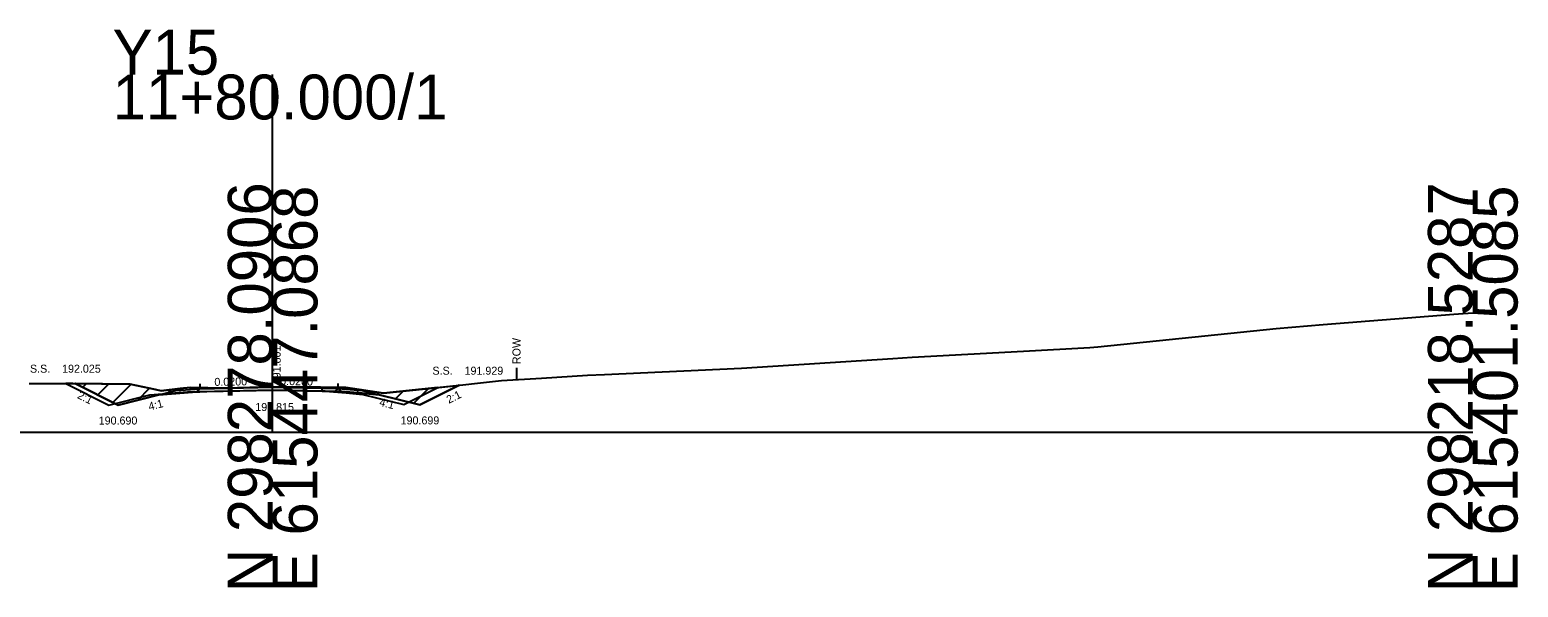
# Model space of a CAD drawing. Extents: x 517327 to 517505, y 114839 to 116885.
# Drawn here: x 517412.2 to 517505.2, y 115838.7 to 115873.5 of the extents above; entities that cross this region are included whole.
import ezdxf

# ---------------------------------------------------------------- set-up
doc = ezdxf.new("R2010")
doc.units = 0
for name, color, linetype in [('Exist XS Ground Line', 7, 'Continuous'), ('Old_Level_60', 7, 'Continuous'), ('Old_Level_63', 7, 'Continuous'), ('Prop XS Dump Level', 7, 'Continuous'), ('Prop XS Earthwork Shape', 7, 'Continuous'), ('Prop XS Elevation Labels', 7, 'Continuous'), ('Prop XS EOT Tick Mark', 7, 'Continuous'), ('Prop XS Exc Vertical Line 2', 7, 'Continuous'), ('Prop XS Finish Grade', 7, 'Continuous'), ('Prop XS Finish Grade Earthwork', 7, 'Continuous'), ('Prop XS Finish Grade Pavement', 7, 'Continuous'), ('Prop XS Hydro Elevations', 7, 'Continuous'), ('Prop XS Label Text', 7, 'Continuous'), ('Prop XS Pvmt Edge Slope', 7, 'Continuous'), ('Prop XS SE Text', 7, 'Continuous'), ('Prop XS Side Slope Text', 7, 'Continuous'), ('Prop XS Subgrade Earthwork', 7, 'Continuous'), ('Prop XS Suitable Common Exc Shape', 7, 'Continuous'), ('Scratch_Level_0', 7, 'Continuous')]:
    doc.layers.add(name, color=color, linetype=linetype)

msp = doc.modelspace()

# ---------------------------------------------------------------- linework, layer by layer
at = {"layer": 'Exist XS Ground Line'}
for p, q in [((517493.021, 115855.082), (517501.19, 115855.736)), ((517501.19, 115855.736), (517502.365, 115855.809)), ((517478.928, 115853.694), (517490.077, 115854.845)), ((517490.077, 115854.845), (517493.021, 115855.082)), ((517467.33, 115853.036), (517474.278, 115853.417)), ((517474.278, 115853.417), (517478.423, 115853.642)), ((517478.423, 115853.642), (517478.928, 115853.694)), ((517456.669, 115852.348), (517466.119, 115852.957)), ((517466.119, 115852.957), (517467.33, 115853.036)), ((517437.742, 115851.155), (517441.67, 115851.58)), ((517441.67, 115851.58), (517444.162, 115851.73)), ((517444.162, 115851.73), (517447.037, 115851.914)), ((517447.037, 115851.914), (517448.104, 115851.955)), ((517448.104, 115851.955), (517456.669, 115852.348)), ((517412.146, 115851.401), (517414.888, 115851.391)), ((517414.888, 115851.391), (517418.466, 115851.364)), ((517418.466, 115851.364), (517420.041, 115851.02)), ((517420.041, 115851.02), (517420.399, 115850.933)), ((517420.399, 115850.933), (517421.585, 115851.079)), ((517421.585, 115851.079), (517422.241, 115851.15)), ((517422.241, 115851.15), (517424.427, 115851.101)), ((517424.427, 115851.101), (517427.438, 115851.181)), ((517427.438, 115851.181), (517430.352, 115851.168)), ((517430.352, 115851.168), (517431.95, 115851.141)), ((517431.95, 115851.141), (517434.302, 115850.789)), ((517434.302, 115850.789), (517437.742, 115851.155))]:
    msp.add_line(p, q, dxfattribs=at)
at = {"layer": 'Old_Level_63'}
for p, q in [((517427.365, 115848.365), (517427.365, 115870.698)), ((517352.365, 115848.365), (517427.365, 115848.365)), ((517427.365, 115848.365), (517502.365, 115848.365))]:
    msp.add_line(p, q, dxfattribs=at)
at = {"layer": 'Prop XS Dump Level'}
for p, q in [((517422.807, 115851.075), (517427.365, 115851.166)), ((517427.365, 115851.166), (517431.468, 115851.084))]:
    msp.add_line(p, q, dxfattribs=at)
at = {"layer": 'Prop XS Earthwork Shape'}
msp.add_lwpolyline([(517431.468, 115850.894), (517427.365, 115850.976), (517422.807, 115850.885), (517422.613, 115850.881), (517421.307, 115850.776), (517420.257, 115850.692), (517417.707, 115850.055), (517415.035, 115851.39), (517418.466, 115851.364), (517420.041, 115851.02), (517420.399, 115850.933), (517421.585, 115851.079), (517422.241, 115851.15), (517424.427, 115851.101), (517427.438, 115851.181), (517430.352, 115851.168), (517431.95, 115851.141), (517434.302, 115850.789), (517437.742, 115851.155), (517439.028, 115851.294), (517436.568, 115850.064), (517434.017, 115850.701), (517432.968, 115850.785), (517431.662, 115850.89)], close=True, dxfattribs=at)
at = {"layer": 'Prop XS EOT Tick Mark'}
for p, q in [((517422.807, 115851.379), (517422.807, 115851.075)), ((517431.468, 115851.084), (517431.468, 115851.389))]:
    msp.add_line(p, q, dxfattribs=at)
at = {"layer": 'Prop XS Exc Vertical Line 2'}
msp.add_line((517442.605, 115852.386), (517442.605, 115851.636), dxfattribs=at)
at = {"layer": 'Prop XS Finish Grade'}
for p, q in [((517420.257, 115850.692), (517421.307, 115850.955)), ((517421.307, 115850.955), (517422.807, 115851.075)), ((517431.468, 115851.084), (517432.968, 115850.964)), ((517432.968, 115850.964), (517434.017, 115850.701))]:
    msp.add_line(p, q, dxfattribs=at)
at = {"layer": 'Prop XS Finish Grade Earthwork'}
for p, q in [((517415.035, 115851.39), (517417.707, 115850.055)), ((517417.707, 115850.055), (517420.257, 115850.692)), ((517434.017, 115850.701), (517436.568, 115850.064)), ((517436.568, 115850.064), (517439.028, 115851.294))]:
    msp.add_line(p, q, dxfattribs=at)
at = {"layer": 'Prop XS Finish Grade Pavement'}
for p, q in [((517427.365, 115851.166), (517422.807, 115851.075)), ((517431.468, 115851.084), (517427.365, 115851.166))]:
    msp.add_line(p, q, dxfattribs=at)
at = {"layer": 'Prop XS Pvmt Edge Slope'}
for p, q in [((517422.613, 115850.881), (517422.807, 115851.075)), ((517431.468, 115851.084), (517431.662, 115850.89))]:
    msp.add_line(p, q, dxfattribs=at)
at = {"layer": 'Prop XS Subgrade Earthwork'}
for p, q in [((517420.257, 115850.692), (517421.307, 115850.776)), ((517421.307, 115850.776), (517422.613, 115850.881)), ((517422.613, 115850.881), (517422.807, 115850.885)), ((517427.365, 115850.976), (517422.807, 115850.885)), ((517431.468, 115850.894), (517427.365, 115850.976)), ((517431.468, 115850.894), (517431.662, 115850.89)), ((517431.662, 115850.89), (517432.968, 115850.785)), ((517432.968, 115850.785), (517434.017, 115850.701))]:
    msp.add_line(p, q, dxfattribs=at)
at = {"layer": 'Prop XS Suitable Common Exc Shape'}
msp.add_lwpolyline([(517435.554, 115850.084), (517437.684, 115851.149), (517434.302, 115850.789), (517431.95, 115851.141), (517430.352, 115851.168), (517427.438, 115851.181), (517424.427, 115851.101), (517422.241, 115851.15), (517421.585, 115851.079), (517420.399, 115850.933), (517420.041, 115851.02), (517418.466, 115851.364), (517414.888, 115851.391), (517414.44, 115851.393), (517417.139, 115850.043), (517419.69, 115850.681), (517420.739, 115850.765), (517422.045, 115850.869), (517422.239, 115850.873), (517427.365, 115850.976), (517430.454, 115850.914), (517430.648, 115850.91), (517431.954, 115850.806), (517433.004, 115850.722)], close=True, dxfattribs=at)
at = {"layer": 'Scratch_Level_0'}
for p, q in [((517415.496, 115851.16), (517415.72, 115851.385)), ((517416.438, 115850.689), (517417.124, 115851.374)), ((517417.381, 115850.217), (517418.517, 115851.353)), ((517418.941, 115850.363), (517419.678, 115851.1)), ((517420.827, 115850.835), (517420.999, 115851.007)), ((517431.262, 115850.898), (517431.515, 115851.151)), ((517432.601, 115850.822), (517432.793, 115851.015)), ((517433.903, 115850.711), (517434.023, 115850.831)), ((517435.05, 115850.443), (517435.526, 115850.919)), ((517436.181, 115850.16), (517437.108, 115851.088))]:
    msp.add_line(p, q, dxfattribs=at)
for points in [[(517415.035, 115851.39), (517417.707, 115850.055), (517420.257, 115850.692), (517421.307, 115850.955), (517422.238, 115851.029), (517422.241, 115851.15), (517421.585, 115851.079), (517420.399, 115850.933), (517420.041, 115851.02), (517418.466, 115851.364), (517415.035, 115851.39)], [(517439.028, 115851.294), (517436.568, 115850.064), (517434.017, 115850.701), (517431.662, 115850.89), (517430.648, 115850.91), (517430.454, 115850.914), (517430.46, 115851.174), (517431.95, 115851.141), (517434.302, 115850.789)]]:
    msp.add_lwpolyline(points, close=True, dxfattribs=at)

# ---------------------------------------------------------------- texts
at = {"layer": 'Old_Level_60'}
msp.add_text('191.815', height=0.5, dxfattribs=at).set_placement((517426.282, 115849.679))
at = {"layer": 'Old_Level_63'}
for s, p in [('Y15', (517417.362, 115870.698)), ('11+80.000/1', (517417.365, 115867.898))]:
    msp.add_text(s, height=2.8, dxfattribs=at).set_placement(p)
for s, p in [('N 298278.0906', (517427.365, 115838.364)), ('E 615447.0868', (517430.165, 115838.365)), ('N 298218.5287', (517502.365, 115838.365)), ('E 615401.5085', (517505.165, 115838.365))]:
    msp.add_text(s, height=2.8, rotation=90, dxfattribs=at).set_placement(p)
at = {"layer": 'Prop XS Dump Level'}
for p in [(517421.307, 115850.942), (517432.968, 115850.952)]:
    msp.add_text('Case1', height=0.0122, dxfattribs=at).set_placement(p)
at = {"layer": 'Prop XS Elevation Labels'}
msp.add_text(' 191.801', height=0.5, rotation=90, dxfattribs=at).set_placement((517427.865, 115851.166))
at = {"layer": 'Prop XS Exc Vertical Line 2'}
msp.add_text('ROW', height=0.5, rotation=90, dxfattribs=at).set_placement((517442.855, 115852.611))
at = {"layer": 'Prop XS Hydro Elevations'}
for s, p in [('S.S.    192.025', (517412.201, 115852.073)), ('S.S.    191.929', (517437.353, 115851.948))]:
    msp.add_text(s, height=0.5, dxfattribs=at).set_placement(p)
at = {"layer": 'Prop XS Label Text'}
for rotation, p in [(14.03624, (517419.668, 115849.708)), (345.96376, (517434, 115850.017))]:
    msp.add_text('4:1', height=0.5, rotation=rotation, dxfattribs=at).set_placement(p)
at = {"layer": 'Prop XS SE Text'}
for rotation, p in [(1.14576, (517423.73, 115851.245)), (358.85424, (517427.837, 115851.309))]:
    msp.add_text('0.0200', height=0.5, rotation=rotation, dxfattribs=at).set_placement(p)
at = {"layer": 'Prop XS Side Slope Text'}
for rotation, p in [(333.43495, (517415.121, 115850.505)), (26.56505, (517438.377, 115850.126))]:
    msp.add_text('2:1', height=0.5, rotation=rotation, dxfattribs=at).set_placement(p)
for s, p in [('190.690', (517416.496, 115848.835)), ('190.699', (517435.363, 115848.844))]:
    msp.add_text(s, height=0.5, dxfattribs=at).set_placement(p)

doc.saveas('drawing.dxf')
